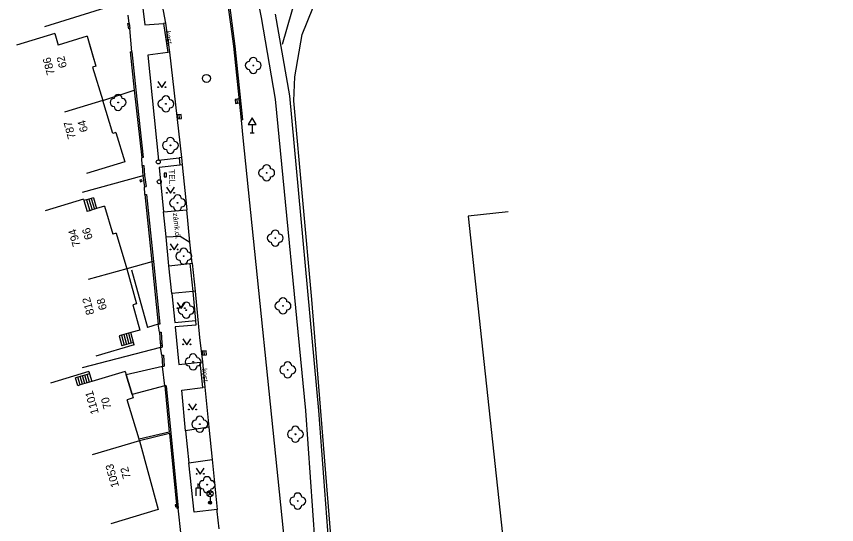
# Model space of a CAD drawing. Extents: x -539694 to -539148, y -1156467 to -1155920.
# Drawn here: x -539663.4 to -539561, y -1156186.2 to -1156122.8 of the extents above; entities that cross this region are included whole.
import ezdxf

# ---------------------------------------------------------------- set-up
doc = ezdxf.new("R2010")
doc.units = 0
for name, color, linetype in [('Vrstva 10', 7, 'Continuous'), ('Vrstva 11', 7, 'Continuous'), ('Vrstva 22', 7, 'Continuous'), ('Vrstva 23', 7, 'Continuous'), ('Vrstva 24', 7, 'Continuous'), ('Vrstva 27', 7, 'Continuous'), ('Vrstva 28', 7, 'Continuous'), ('Vrstva 33', 7, 'Continuous'), ('Vrstva 34', 7, 'Continuous'), ('Vrstva 36', 7, 'Continuous'), ('Vrstva 38', 7, 'Continuous'), ('Vrstva 40', 7, 'Continuous'), ('Vrstva 41', 7, 'Continuous'), ('Vrstva 46', 7, 'Continuous'), ('Vrstva 47', 7, 'Continuous'), ('Vrstva 5', 7, 'Continuous'), ('Vrstva 6', 7, 'Continuous'), ('Vrstva 7', 7, 'Continuous'), ('Vrstva 8', 7, 'Continuous')]:
    doc.layers.add(name, color=color, linetype=linetype)

msp = doc.modelspace()

# ---------------------------------------------------------------- linework, layer by layer
at = {"layer": 'Vrstva 10'}
msp.add_line((-539629.3, -1156194.54), (-539635.12, -1156137.96), dxfattribs=at)
at = {"layer": 'Vrstva 11'}
for p, q in [((-539634.77, -1156113.57), (-539632.86, -1156122.94)), ((-539636.29, -1156126.52), (-539637.4, -1156118.11)), ((-539637.26, -1156118.09), (-539636.15, -1156126.5)), ((-539629.29, -1156132.71), (-539631.05, -1156122.54)), ((-539632.86, -1156122.94), (-539631.12, -1156133.12)), ((-539644.5, -1156127.29), (-539647.02, -1156127.65)), ((-539647.02, -1156127.65), (-539645.69, -1156140.76)), ((-539644.29, -1156127.25), (-539642.816, -1156140.412)), ((-539625.639, -1156171.992), (-539629.29, -1156132.71)), ((-539631.12, -1156133.12), (-539627.3, -1156171.99)), ((-539642.816, -1156140.412), (-539643.11, -1156140.44)), ((-539642.816, -1156140.412), (-539642.72, -1156141.34)), ((-539645.61, -1156141.67), (-539645.04, -1156147.18)), ((-539642.72, -1156141.34), (-539642.15, -1156146.95)), ((-539654.672, -1156145.697), (-539654.269, -1156147.048)), ((-539654.384, -1156145.611), (-539653.981, -1156146.962)), ((-539654.097, -1156145.525), (-539653.694, -1156146.876)), ((-539653.81, -1156145.44), (-539653.407, -1156146.791)), ((-539644.38, -1156153.95), (-539641.77, -1156153.62)), ((-539641.77, -1156153.62), (-539641.47, -1156153.58)), ((-539649.037, -1156154.423), (-539647.05, -1156161.63)), ((-539641.1, -1156157.11), (-539640.54, -1156162.89)), ((-539645.718, -1156161.22), (-539647.05, -1156161.63)), ((-539650.012, -1156162.502), (-539650.301, -1156162.582)), ((-539649.723, -1156162.422), (-539650.012, -1156162.502)), ((-539650.012, -1156162.502), (-539649.677, -1156163.739)), ((-539649.434, -1156162.343), (-539649.723, -1156162.422)), ((-539649.723, -1156162.422), (-539649.39, -1156163.653)), ((-539649.145, -1156162.263), (-539649.434, -1156162.343)), ((-539649.434, -1156162.343), (-539649.102, -1156163.568)), ((-539650.301, -1156162.582), (-539650.59, -1156162.661)), ((-539650.59, -1156162.661), (-539650.252, -1156163.91)), ((-539650.301, -1156162.582), (-539649.965, -1156163.825)), ((-539640.54, -1156162.89), (-539640.19, -1156165.93)), ((-539645.179, -1156166.472), (-539649.702, -1156167.522)), ((-539643.14, -1156166.24), (-539640.47, -1156165.96)), ((-539654.881, -1156168.626), (-539655.174, -1156167.657)), ((-539654.594, -1156168.539), (-539654.887, -1156167.57)), ((-539654.307, -1156168.452), (-539654.6, -1156167.483)), ((-539655.742, -1156168.886), (-539656.035, -1156167.917)), ((-539655.455, -1156168.8), (-539655.748, -1156167.831)), ((-539655.168, -1156168.713), (-539655.461, -1156167.744)), ((-539654.881, -1156168.626), (-539655.168, -1156168.713)), ((-539654.594, -1156168.539), (-539654.881, -1156168.626)), ((-539654.307, -1156168.452), (-539654.594, -1156168.539)), ((-539654.02, -1156168.365), (-539654.307, -1156168.452)), ((-539655.455, -1156168.8), (-539655.742, -1156168.886)), ((-539655.168, -1156168.713), (-539655.455, -1156168.8)), ((-539644.899, -1156168.918), (-539648.959, -1156169.982)), ((-539642.76, -1156169.44), (-539640.14, -1156169.1)), ((-539642.29, -1156174.54), (-539642.76, -1156169.44)), ((-539639.89, -1156169.07), (-539639.38, -1156174.05)), ((-539627.3, -1156171.99), (-539625.77, -1156194.09)), ((-539623.95, -1156194.94), (-539625.639, -1156171.992)), ((-539639.38, -1156174.05), (-539638.98, -1156178.08)), ((-539641.23, -1156184.68), (-539641.87, -1156178.52)), ((-539638.98, -1156178.08), (-539638.35, -1156184.32)), ((-539638.35, -1156184.32), (-539641.23, -1156184.68))]:
    msp.add_line(p, q, dxfattribs=at)
for points in [[(-539645.52, -1156119.87), (-539647.81, -1156120.39), (-539647.39, -1156123.87), (-539645.07, -1156123.69)], [(-539645.52, -1156119.87), (-539644.8, -1156123.64), (-539645.07, -1156123.69), (-539644.5, -1156127.29)], [(-539644.8, -1156123.64), (-539644.29, -1156127.25), (-539644.5, -1156127.29)], [(-539635.12, -1156137.96), (-539635.31, -1156135.74), (-539636.29, -1156126.52)], [(-539636.15, -1156126.5), (-539635.17, -1156135.73), (-539635.31, -1156135.74)], [(-539645.69, -1156140.76), (-539643.11, -1156140.44), (-539643.01, -1156141.36)], [(-539642.72, -1156141.34), (-539643.01, -1156141.36), (-539645.61, -1156141.67)], [(-539653.81, -1156145.44), (-539654.097, -1156145.525), (-539654.384, -1156145.611), (-539654.672, -1156145.697), (-539655.001, -1156145.795)], [(-539644.38, -1156153.95), (-539644.72, -1156150.3), (-539645.04, -1156147.18), (-539642.15, -1156146.95)], [(-539641.47, -1156153.58), (-539641.76, -1156150.96), (-539642.15, -1156146.95)], [(-539644.72, -1156150.3), (-539642.96, -1156150.21), (-539641.76, -1156150.96)], [(-539641.39, -1156157.14), (-539644.03, -1156157.4), (-539644.38, -1156153.95)], [(-539641.77, -1156153.62), (-539641.39, -1156157.14), (-539641.07, -1156160.77)], [(-539641.47, -1156153.58), (-539641.1, -1156157.11), (-539641.39, -1156157.14)], [(-539644.03, -1156157.4), (-539643.64, -1156161.02), (-539641.07, -1156160.77)], [(-539641.07, -1156160.77), (-539641.01, -1156161.34), (-539643.58, -1156161.55), (-539643.14, -1156166.24)], [(-539648.81, -1156163.48), (-539649.102, -1156163.568), (-539649.39, -1156163.653), (-539649.677, -1156163.739), (-539649.965, -1156163.825), (-539650.252, -1156163.91)], [(-539639.89, -1156169.07), (-539640.14, -1156169.1), (-539640.47, -1156165.96), (-539640.19, -1156165.93), (-539639.89, -1156169.07)], [(-539654.313, -1156167.397), (-539654.6, -1156167.483), (-539654.887, -1156167.57), (-539655.174, -1156167.657), (-539655.461, -1156167.744), (-539655.748, -1156167.831), (-539656.035, -1156167.917)], [(-539639.38, -1156174.05), (-539642.29, -1156174.54), (-539641.87, -1156178.52), (-539638.98, -1156178.08)], [(-539638.09, -1156186.77), (-539638.34, -1156184.59), (-539638.35, -1156184.32)]]:
    msp.add_lwpolyline(points, dxfattribs=at)
at = {"layer": 'Vrstva 22'}
for centre in [(-539633.84, -1156128.92), (-539650.72, -1156133.54), (-539644.75, -1156133.72), (-539644.19, -1156138.9), (-539632.17, -1156142.32), (-539643.3, -1156146.08), (-539631.09, -1156150.47), (-539642.53, -1156152.73), (-539642.21, -1156159.46), (-539630.13, -1156158.93), (-539641.35, -1156165.92), (-539629.54, -1156166.92), (-539640.52, -1156173.69), (-539628.58, -1156174.95), (-539639.61, -1156181.24), (-539628.29, -1156183.28)]:
    msp.add_circle(centre, 0.05, dxfattribs=at)
for centre, start, end in [((-539634.34, -1156128.92), 90, 270), ((-539633.84, -1156128.42), 0, 180), ((-539633.34, -1156128.92), 270, 90), ((-539633.84, -1156129.42), 180, 0), ((-539650.72, -1156133.04), 0, 180), ((-539644.75, -1156133.22), 0, 180), ((-539651.22, -1156133.54), 90, 270), ((-539650.22, -1156133.54), 270, 90), ((-539645.25, -1156133.72), 90, 270), ((-539644.25, -1156133.72), 270, 90), ((-539650.72, -1156134.04), 180, 0), ((-539644.75, -1156134.22), 180, 0), ((-539644.19, -1156138.4), 0, 180), ((-539644.69, -1156138.9), 90, 270), ((-539643.69, -1156138.9), 270, 90), ((-539644.19, -1156139.4), 180, 0), ((-539632.67, -1156142.32), 90, 270), ((-539632.17, -1156141.82), 0, 180), ((-539631.67, -1156142.32), 270, 90), ((-539632.17, -1156142.82), 180, 0), ((-539643.3, -1156145.58), 0, 180), ((-539643.8, -1156146.08), 90, 270), ((-539642.8, -1156146.08), 270, 90), ((-539643.3, -1156146.58), 180, 0), ((-539631.59, -1156150.47), 90, 270), ((-539631.09, -1156149.97), 0, 180), ((-539630.59, -1156150.47), 270, 90), ((-539631.09, -1156150.97), 180, 0), ((-539643.03, -1156152.73), 90, 270), ((-539642.53, -1156152.23), 0, 180), ((-539642.03, -1156152.73), 270, 90), ((-539642.53, -1156153.23), 180, 0), ((-539642.21, -1156158.96), 0, 180), ((-539630.63, -1156158.93), 90, 270), ((-539630.13, -1156158.43), 0, 180), ((-539629.63, -1156158.93), 270, 90), ((-539642.71, -1156159.46), 90, 270), ((-539641.71, -1156159.46), 270, 90), ((-539630.13, -1156159.43), 180, 0), ((-539642.21, -1156159.96), 180, 0), ((-539641.85, -1156165.92), 90, 270), ((-539641.35, -1156165.42), 0, 180), ((-539640.85, -1156165.92), 270, 90), ((-539641.35, -1156166.42), 180, 0), ((-539630.04, -1156166.92), 90, 270), ((-539629.54, -1156166.42), 0, 180), ((-539629.04, -1156166.92), 270, 90), ((-539629.54, -1156167.42), 180, 0), ((-539640.52, -1156173.19), 0, 180), ((-539641.02, -1156173.69), 90, 270), ((-539640.02, -1156173.69), 270, 90), ((-539640.52, -1156174.19), 180, 0), ((-539629.08, -1156174.95), 90, 270), ((-539628.58, -1156174.45), 0, 180), ((-539628.08, -1156174.95), 270, 90), ((-539628.58, -1156175.45), 180, 0), ((-539640.11, -1156181.24), 90, 270), ((-539639.61, -1156180.74), 0, 180), ((-539639.11, -1156181.24), 270, 90), ((-539639.61, -1156181.74), 180, 0), ((-539628.79, -1156183.28), 90, 270), ((-539628.29, -1156182.78), 0, 180), ((-539627.79, -1156183.28), 270, 90), ((-539628.29, -1156183.78), 180, 0)]:
    msp.add_arc(centre, 0.5, start, end, dxfattribs=at)
at = {"layer": 'Vrstva 23'}
msp.add_lwpolyline([(-539630.21, -1156126.28), (-539627.31, -1156116.28), (-539623.24, -1156107.31), (-539618.5, -1156099.79), (-539610.92, -1156093.46), (-539603.15, -1156087.27), (-539595.85, -1156082.5), (-539586.69, -1156078.25), (-539577.71, -1156074.31), (-539568.17, -1156069.49), (-539560.98, -1156065.43)], dxfattribs=at)
at = {"layer": 'Vrstva 24'}
for p, q in [((-539644.68, -1156142.356), (-539644.98, -1156142.369)), ((-539644.98, -1156142.369), (-539644.96, -1156142.83)), ((-539644.96, -1156142.83), (-539644.66, -1156142.817)), ((-539644.66, -1156142.817), (-539644.68, -1156142.356)), ((-539647.749, -1156143.194), (-539647.99, -1156143.259)), ((-539647.99, -1156143.259), (-539647.943, -1156143.433)), ((-539647.943, -1156143.433), (-539647.702, -1156143.368)), ((-539647.702, -1156143.368), (-539647.749, -1156143.194)), ((-539645.457, -1156163.59), (-539645.258, -1156163.576)), ((-539645.439, -1156163.84), (-539645.24, -1156163.826)), ((-539643.414, -1156183.726), (-539643.593, -1156183.745)), ((-539643.593, -1156183.745), (-539643.567, -1156183.993)), ((-539643.567, -1156183.993), (-539643.388, -1156183.974)), ((-539643.388, -1156183.974), (-539643.414, -1156183.726))]:
    msp.add_line(p, q, dxfattribs=at)
at = {"layer": 'Vrstva 27'}
for p, q in [((-539635.794, -1156133.629), (-539635.846, -1156133.131)), ((-539643.045, -1156135.559), (-539643.095, -1156135.061)), ((-539639.935, -1156165.069), (-539639.985, -1156164.571))]:
    msp.add_line(p, q, dxfattribs=at)
for points in [[(-539635.545, -1156133.602), (-539635.598, -1156133.105), (-539636.095, -1156133.158), (-539636.042, -1156133.655)], [(-539642.796, -1156135.533), (-539642.847, -1156135.036), (-539643.344, -1156135.087), (-539643.293, -1156135.584)], [(-539639.686, -1156165.043), (-539639.737, -1156164.546), (-539640.234, -1156164.597), (-539640.183, -1156165.094)]]:
    msp.add_lwpolyline(points, close=True, dxfattribs=at)
msp.add_circle((-539639.69, -1156130.54), 0.5, dxfattribs=at)
at = {"layer": 'Vrstva 28'}
for centre in [(-539645.71, -1156140.96), (-539645.58, -1156143.44)]:
    msp.add_circle(centre, 0.25, dxfattribs=at)
at = {"layer": 'Vrstva 33'}
for p, q in [((-539639.505, -1156182.63), (-539638.975, -1156182.1)), ((-539639.505, -1156182.1), (-539638.975, -1156182.63)), ((-539639.24, -1156182.74), (-539639.24, -1156183.49))]:
    msp.add_line(p, q, dxfattribs=at)
for centre, radius in [((-539639.24, -1156182.365), 0.375), ((-539639.24, -1156183.49), 0.2), ((-539639.24, -1156183.49), 0.145), ((-539639.24, -1156183.49), 0.0876)]:
    msp.add_circle(centre, radius, dxfattribs=at)
at = {"layer": 'Vrstva 34'}
for p, q in [((-539633.97, -1156136.312), (-539633.97, -1156137.33)), ((-539634.22, -1156137.33), (-539633.72, -1156137.33))]:
    msp.add_line(p, q, dxfattribs=at)
msp.add_lwpolyline([(-539634.47, -1156136.312), (-539633.47, -1156136.312), (-539633.97, -1156135.446)], close=True, dxfattribs=at)
at = {"layer": 'Vrstva 36'}
for points in [[(-539645.763, -1156130.943), (-539645.263, -1156131.693), (-539644.763, -1156130.943)], [(-539644.676, -1156144.12), (-539644.176, -1156144.87), (-539643.676, -1156144.12)], [(-539644.24, -1156151.2), (-539643.74, -1156151.95), (-539643.24, -1156151.2)], [(-539643.35, -1156158.51), (-539642.85, -1156159.26), (-539642.35, -1156158.51)], [(-539642.64, -1156163.03), (-539642.14, -1156163.78), (-539641.64, -1156163.03)], [(-539641.93, -1156171.15), (-539641.43, -1156171.9), (-539640.93, -1156171.15)], [(-539640.956, -1156179.177), (-539640.456, -1156179.927), (-539639.956, -1156179.177)]]:
    msp.add_lwpolyline(points, dxfattribs=at)
for centre in [(-539645.713, -1156131.643), (-539644.814, -1156131.643), (-539644.626, -1156144.82), (-539643.727, -1156144.82), (-539644.19, -1156151.9), (-539643.291, -1156151.9), (-539643.3, -1156159.21), (-539642.401, -1156159.21), (-539642.59, -1156163.73), (-539641.691, -1156163.73), (-539641.88, -1156171.85), (-539640.981, -1156171.85), (-539640.906, -1156179.877), (-539640.007, -1156179.877)]:
    msp.add_circle(centre, 0.05, dxfattribs=at)
at = {"layer": 'Vrstva 38'}
msp.add_line((-539640.74, -1156181.63), (-539640.74, -1156181.1), dxfattribs=at)
msp.add_lwpolyline([(-539640.99, -1156182.63), (-539640.99, -1156181.63), (-539640.49, -1156181.63), (-539640.49, -1156182.63)], dxfattribs=at)
at = {"layer": 'Vrstva 5'}
for p, q in [((-539658.645, -1156124.946), (-539663.428, -1156126.402)), ((-539658.645, -1156124.946), (-539658.224, -1156126.386)), ((-539654.59, -1156125.28), (-539658.224, -1156126.386)), ((-539654.59, -1156125.28), (-539653.5, -1156129.01)), ((-539653.5, -1156129.01), (-539653.905, -1156129.133)), ((-539653.905, -1156129.133), (-539652.64, -1156133.29)), ((-539652.64, -1156133.29), (-539657.423, -1156134.746)), ((-539651.388, -1156137.402), (-539652.64, -1156133.29)), ((-539651.02, -1156137.29), (-539651.388, -1156137.402)), ((-539651.02, -1156137.29), (-539649.9, -1156140.97)), ((-539649.9, -1156140.97), (-539654.683, -1156142.426)), ((-539655.05, -1156145.63), (-539659.842, -1156147.058)), ((-539655.05, -1156145.63), (-539655.001, -1156145.795)), ((-539655.001, -1156145.795), (-539654.598, -1156147.146)), ((-539654.269, -1156147.048), (-539654.598, -1156147.146)), ((-539653.981, -1156146.962), (-539654.269, -1156147.048)), ((-539653.694, -1156146.876), (-539653.981, -1156146.962)), ((-539653.407, -1156146.791), (-539653.694, -1156146.876)), ((-539652.43, -1156146.5), (-539653.407, -1156146.791)), ((-539652.43, -1156146.5), (-539651.39, -1156149.991)), ((-539602.019, -1156147.202), (-539606.99, -1156147.74)), ((-539606.99, -1156147.74), (-539602.059, -1156193.342)), ((-539650.95, -1156149.86), (-539651.39, -1156149.991)), ((-539650.95, -1156149.86), (-539649.63, -1156154.29)), ((-539649.63, -1156154.29), (-539654.45, -1156155.619)), ((-539649.63, -1156154.29), (-539648.42, -1156158.68)), ((-539648.42, -1156158.68), (-539648.877, -1156158.806)), ((-539648.877, -1156158.806), (-539648.01, -1156161.95)), ((-539648.01, -1156161.95), (-539649.145, -1156162.263)), ((-539648.81, -1156163.48), (-539649.145, -1156162.263)), ((-539648.73, -1156163.77), (-539648.81, -1156163.48)), ((-539648.73, -1156163.77), (-539653.522, -1156165.198)), ((-539654.4, -1156167.11), (-539659.186, -1156168.556)), ((-539654.4, -1156167.11), (-539654.313, -1156167.397)), ((-539654.313, -1156167.397), (-539654.02, -1156168.365)), ((-539649.83, -1156167.1), (-539654.02, -1156168.365)), ((-539649.83, -1156167.1), (-539649.702, -1156167.522)), ((-539649.702, -1156167.522), (-539648.959, -1156169.982)), ((-539648.83, -1156170.41), (-539649.584, -1156170.638)), ((-539648.092, -1156175.578), (-539649.584, -1156170.638)), ((-539648.959, -1156169.982), (-539648.83, -1156170.41)), ((-539648.04, -1156175.75), (-539653.952, -1156177.536)), ((-539648.04, -1156175.75), (-539648.092, -1156175.578)), ((-539648.04, -1156175.75), (-539645.74, -1156184.32)), ((-539645.74, -1156184.32), (-539651.652, -1156186.106))]:
    msp.add_line(p, q, dxfattribs=at)
at = {"layer": 'Vrstva 6'}
for p, q in [((-539653.732, -1156128.244), (-539654.359, -1156126.041)), ((-539648.96, -1156169.98), (-539649.707, -1156167.521))]:
    msp.add_line(p, q, dxfattribs=at)
at = {"layer": 'Vrstva 7'}
for p, q in [((-539649.868, -1156121.004), (-539659.91, -1156124.09)), ((-539627.75, -1156125.06), (-539626.39, -1156121.77)), ((-539649.547, -1156123.711), (-539649.35, -1156123.68)), ((-539649.547, -1156123.711), (-539649.447, -1156124.341)), ((-539649.25, -1156124.31), (-539649.447, -1156124.341)), ((-539649.35, -1156123.68), (-539649.25, -1156124.31)), ((-539628.66, -1156130.34), (-539627.75, -1156125.06)), ((-539649.208, -1156127.24), (-539649.01, -1156127.22)), ((-539649.208, -1156127.24), (-539648.718, -1156132.002)), ((-539649.01, -1156127.22), (-539648.52, -1156131.98)), ((-539628.79, -1156133.33), (-539628.66, -1156130.34)), ((-539652.64, -1156133.29), (-539648.718, -1156132.002)), ((-539648.718, -1156132.002), (-539647.778, -1156140.452)), ((-539648.52, -1156131.98), (-539647.58, -1156140.43)), ((-539626.515, -1156158.135), (-539628.79, -1156133.33)), ((-539647.58, -1156140.43), (-539647.778, -1156140.452)), ((-539647.709, -1156141.431), (-539647.51, -1156141.42)), ((-539647.709, -1156141.431), (-539647.639, -1156142.681)), ((-539647.51, -1156141.42), (-539647.44, -1156142.67)), ((-539647.639, -1156142.681), (-539655.21, -1156144.78)), ((-539647.639, -1156142.681), (-539647.44, -1156142.67)), ((-539647.639, -1156142.681), (-539647.427, -1156144.06)), ((-539647.44, -1156142.67), (-539647.23, -1156144.03)), ((-539647.427, -1156144.06), (-539647.23, -1156144.03)), ((-539647.378, -1156145.04), (-539647.18, -1156145.02)), ((-539647.378, -1156145.04), (-539646.515, -1156153.452)), ((-539647.18, -1156145.02), (-539646.32, -1156153.4)), ((-539646.515, -1156153.452), (-539645.718, -1156161.22)), ((-539646.32, -1156153.4), (-539645.52, -1156161.2)), ((-539621.153, -1156225.416), (-539626.515, -1156158.135)), ((-539645.52, -1156161.2), (-539645.718, -1156161.22)), ((-539645.559, -1156162.204), (-539645.36, -1156162.19)), ((-539645.419, -1156164.114), (-539655.193, -1156166.641)), ((-539645.419, -1156164.114), (-539645.22, -1156164.1)), ((-539645.269, -1156165.082), (-539645.07, -1156165.07)), ((-539645.269, -1156165.082), (-539645.179, -1156166.472)), ((-539645.07, -1156165.07), (-539644.98, -1156166.46)), ((-539645.179, -1156166.472), (-539644.98, -1156166.46)), ((-539644.72, -1156168.9), (-539644.899, -1156168.918)), ((-539644.899, -1156168.918), (-539644.334, -1156174.691)), ((-539644.72, -1156168.9), (-539644.14, -1156174.83)), ((-539644.334, -1156174.691), (-539648.092, -1156175.578)), ((-539644.14, -1156174.83), (-539643.23, -1156184.15)), ((-539644.287, -1156174.865), (-539643.379, -1156184.165)), ((-539643.379, -1156184.165), (-539643.23, -1156184.15))]:
    msp.add_line(p, q, dxfattribs=at)
for points in [[(-539646.32, -1156153.4), (-539646.515, -1156153.452), (-539649.63, -1156154.29)], [(-539645.559, -1156162.204), (-539645.457, -1156163.59), (-539645.439, -1156163.84), (-539645.419, -1156164.114)], [(-539645.36, -1156162.19), (-539645.258, -1156163.576), (-539645.24, -1156163.826), (-539645.22, -1156164.1)], [(-539644.14, -1156174.83), (-539644.287, -1156174.865), (-539648.04, -1156175.75)]]:
    msp.add_lwpolyline(points, dxfattribs=at)
at = {"layer": 'Vrstva 8'}
for p, q in [((-539649.35, -1156123.68), (-539649.46, -1156122.65)), ((-539649.01, -1156127.22), (-539649.25, -1156124.31)), ((-539647.709, -1156141.431), (-539647.778, -1156140.452)), ((-539647.378, -1156145.04), (-539647.427, -1156144.06)), ((-539645.559, -1156162.204), (-539645.718, -1156161.22)), ((-539645.269, -1156165.082), (-539645.419, -1156164.114)), ((-539644.899, -1156168.918), (-539645.179, -1156166.472)), ((-539642.86, -1156187.57), (-539643.23, -1156184.15))]:
    msp.add_line(p, q, dxfattribs=at)

# ---------------------------------------------------------------- texts
at = {"layer": 'Vrstva 40'}
for s, rotation, p in [('kost.', 278.99712, (-539644.82, -1156124.66)), ('zámk.dl.', 275.85603, (-539643.88, -1156147.36)), ('kost.', 275.99949, (-539640.26, -1156166.76))]:
    msp.add_text(s, height=0.65, rotation=rotation, dxfattribs=at).set_placement(p)
at = {"layer": 'Vrstva 41'}
msp.add_text('TEL.', height=0.75, rotation=272.48955, dxfattribs=at).set_placement((-539644.407, -1156141.914))
at = {"layer": 'Vrstva 46'}
for s, rotation, p in [('62', 105.02293, (-539657.093, -1156129.098)), ('64', 105.02293, (-539654.465, -1156137.102)), ('66', 106.59239, (-539653.873, -1156150.506)), ('68', 105.02293, (-539652.095, -1156159.308)), ('70', 105.02293, (-539651.542, -1156171.669)), ('72', 105.02293, (-539649.126, -1156180.364))]:
    msp.add_text(s, height=1, rotation=rotation, dxfattribs=at).set_placement(p)
at = {"layer": 'Vrstva 47'}
for s, rotation, p in [('786', 105.02293, (-539658.619, -1156129.971)), ('787', 105.02293, (-539655.998, -1156137.949)), ('794', 106.59239, (-539655.385, -1156151.383)), ('812', 105.02293, (-539653.694, -1156159.909)), ('1101', 105.02293, (-539653.129, -1156172.313)), ('1053', 105.02293, (-539650.597, -1156181.44))]:
    msp.add_text(s, height=1, rotation=rotation, dxfattribs=at).set_placement(p)

doc.saveas('drawing.dxf')
